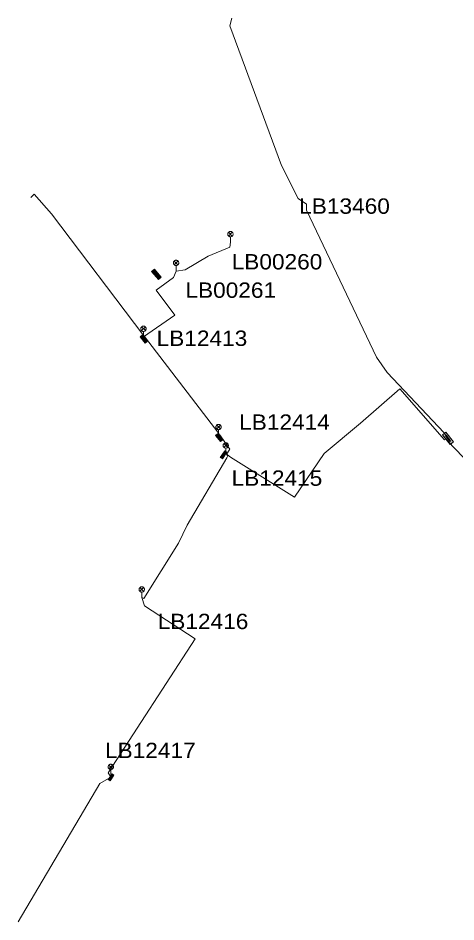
# Model space of a CAD drawing. Extents: x -688091 to -687952, y -973692 to -973558.
# Drawn here: x -688091.4 to -688029.8, y -973685.6 to -973558.3 of the extents above; entities that cross this region are included whole.
import ezdxf

# ---------------------------------------------------------------- set-up
doc = ezdxf.new("R2010")
doc.units = 0
doc.header["$LTSCALE"] = 0.87
doc.layers.add('1', color=7, linetype='Continuous', lineweight=13)

msp = doc.modelspace()

# ---------------------------------------------------------------- hatches: boundary and pattern name
at = {"layer": '1'}
for points in [[(-688071.655, -973595.126), (-688072.624, -973593.981), (-688072.242, -973593.658), (-688071.273, -973594.803)], [(-688071.696, -973594.768), (-688072.277, -973594.081), (-688072.201, -973594.016), (-688071.62, -973594.703)], [(-688073.515, -973604.067), (-688074.242, -973603.208), (-688073.956, -973602.966), (-688073.229, -973603.824)], [(-688073.546, -973603.798), (-688073.982, -973603.283), (-688073.925, -973603.234), (-688073.489, -973603.749)], [(-688062.906, -973617.935), (-688063.633, -973617.076), (-688063.347, -973616.834), (-688062.62, -973617.692)], [(-688062.937, -973617.666), (-688063.373, -973617.151), (-688063.316, -973617.102), (-688062.88, -973617.617)], [(-688030.592, -973618.351), (-688031.674, -973617.001), (-688031.224, -973616.64), (-688030.142, -973617.991)], [(-688030.628, -973617.937), (-688031.277, -973617.127), (-688031.187, -973617.055), (-688030.538, -973617.865)], [(-688062.959, -973620.178), (-688062.339, -973619.24), (-688062.026, -973619.446), (-688062.646, -973620.385)], [(-688062.71, -973620.073), (-688062.338, -973619.51), (-688062.276, -973619.551), (-688062.648, -973620.115)], [(-688078.721, -973665.574), (-688078.197, -973664.783), (-688077.933, -973664.958), (-688078.458, -973665.749)], [(-688078.511, -973665.486), (-688078.196, -973665.011), (-688078.143, -973665.046), (-688078.458, -973665.521)]]:
    msp.add_hatch(color=256, dxfattribs=at).paths.add_polyline_path(points)

# ---------------------------------------------------------------- linework, layer by layer
for p, q in [((-688061.795, -973588.455), (-688061.265, -973588.985)), ((-688061.795, -973588.985), (-688061.265, -973588.455)), ((-688061.53, -973589.87), (-688061.53, -973589.095)), ((-688069.445, -973592.505), (-688068.915, -973593.035)), ((-688069.445, -973593.035), (-688068.915, -973592.505)), ((-688069.18, -973593.92), (-688069.18, -973593.145)), ((-688074.038, -973601.781), (-688073.508, -973602.311)), ((-688074.038, -973602.311), (-688073.508, -973601.781)), ((-688073.773, -973603.196), (-688073.773, -973602.421)), ((-688063.467, -973615.63), (-688062.937, -973616.16)), ((-688063.467, -973616.16), (-688062.937, -973615.63)), ((-688063.202, -973617.045), (-688063.202, -973616.27)), ((-688062.447, -973618.23), (-688061.917, -973618.76)), ((-688062.447, -973618.76), (-688061.917, -973618.23)), ((-688062.182, -973619.645), (-688062.182, -973618.87)), ((-688074.275, -973638.515), (-688073.745, -973639.045)), ((-688074.275, -973639.045), (-688073.745, -973638.515)), ((-688074.01, -973639.93), (-688074.01, -973639.155)), ((-688078.645, -973663.525), (-688078.115, -973664.055)), ((-688078.645, -973664.055), (-688078.115, -973663.525)), ((-688078.38, -973664.94), (-688078.38, -973664.165))]:
    msp.add_line(p, q, dxfattribs=at)
for points in [[(-688061.349, -973558.277), (-688061.626, -973559.369), (-688054.331, -973579.05), (-688051.978, -973583.704), (-688050.82, -973584.51)], [(-688089.624, -973583.543), (-688089.144, -973583.093), (-688086.71, -973585.839), (-688073.712, -973603.033), (-688073.784, -973603.191)], [(-688050.82, -973584.51), (-688050.82, -973585.344), (-688040.947, -973606.062), (-688039.467, -973608.206), (-688031.454, -973616.703), (-688030.924, -973617.509)], [(-688069.18, -973593.92), (-688067.879, -973593.726), (-688064.671, -973591.828), (-688061.593, -973590.543), (-688061.53, -973589.87)], [(-688073.784, -973603.191), (-688069.349, -973600.138), (-688071.998, -973596.628), (-688069.529, -973594.837), (-688069.18, -973593.92)], [(-688073.784, -973603.191), (-688073.646, -973603.122), (-688063.167, -973616.788), (-688063.202, -973617.045)], [(-688062.182, -973619.645), (-688061.501, -973620.15), (-688052.521, -973625.758), (-688048.314, -973619.617), (-688043.211, -973615.339), (-688037.682, -973610.538), (-688031.377, -973617.691), (-688030.924, -973617.509)], [(-688063.202, -973617.045), (-688063.061, -973616.967), (-688061.604, -973619.01), (-688062.056, -973619.668), (-688062.182, -973619.645)], [(-688030.924, -973617.509), (-688030.924, -973617.873), (-688023.518, -973625.63), (-688020.453, -973628.618), (-688019.78, -973628.172)], [(-688074.01, -973639.93), (-688073.721, -973640.061), (-688068.821, -973632.243), (-688067.623, -973629.704), (-688062.047, -973620.222), (-688061.901, -973619.935), (-688062.182, -973619.645)], [(-688074.01, -973639.93), (-688073.617, -973641.103), (-688066.501, -973645.721), (-688078.752, -973664.628), (-688078.301, -973665.283)], [(-688091.419, -973685.626), (-688079.908, -973666.146), (-688078.353, -973665.248)]]:
    msp.add_lwpolyline(points, dxfattribs=at)
for points in [[(-688061.155, -973588.72), (-688061.161, -973588.655), (-688061.178, -973588.592), (-688061.205, -973588.533), (-688061.243, -973588.479), (-688061.289, -973588.433), (-688061.342, -973588.395), (-688061.402, -973588.368), (-688061.465, -973588.351), (-688061.53, -973588.345), (-688061.595, -973588.351), (-688061.658, -973588.368), (-688061.718, -973588.395), (-688061.771, -973588.433), (-688061.817, -973588.479), (-688061.855, -973588.533), (-688061.882, -973588.592), (-688061.899, -973588.655), (-688061.905, -973588.72), (-688061.899, -973588.785), (-688061.882, -973588.848), (-688061.855, -973588.908), (-688061.817, -973588.961), (-688061.771, -973589.007), (-688061.718, -973589.045), (-688061.658, -973589.072), (-688061.595, -973589.089), (-688061.53, -973589.095), (-688061.465, -973589.089), (-688061.402, -973589.072), (-688061.342, -973589.045), (-688061.289, -973589.007), (-688061.243, -973588.961), (-688061.205, -973588.908), (-688061.178, -973588.848), (-688061.161, -973588.785)], [(-688068.805, -973592.77), (-688068.811, -973592.705), (-688068.828, -973592.642), (-688068.855, -973592.582), (-688068.893, -973592.529), (-688068.939, -973592.483), (-688068.992, -973592.445), (-688069.052, -973592.418), (-688069.115, -973592.401), (-688069.18, -973592.395), (-688069.245, -973592.401), (-688069.308, -973592.418), (-688069.368, -973592.445), (-688069.421, -973592.483), (-688069.467, -973592.529), (-688069.505, -973592.582), (-688069.532, -973592.642), (-688069.549, -973592.705), (-688069.555, -973592.77), (-688069.549, -973592.835), (-688069.532, -973592.898), (-688069.505, -973592.958), (-688069.467, -973593.011), (-688069.421, -973593.057), (-688069.368, -973593.095), (-688069.308, -973593.122), (-688069.245, -973593.139), (-688069.18, -973593.145), (-688069.115, -973593.139), (-688069.052, -973593.122), (-688068.992, -973593.095), (-688068.939, -973593.057), (-688068.893, -973593.011), (-688068.855, -973592.958), (-688068.828, -973592.898), (-688068.811, -973592.835)], [(-688071.655, -973595.126), (-688072.624, -973593.981), (-688072.242, -973593.658), (-688071.273, -973594.803)], [(-688071.655, -973595.126), (-688072.624, -973593.981), (-688072.242, -973593.658), (-688071.273, -973594.803)], [(-688071.696, -973594.768), (-688072.277, -973594.081), (-688072.201, -973594.016), (-688071.62, -973594.703)], [(-688073.398, -973602.046), (-688073.404, -973601.981), (-688073.421, -973601.918), (-688073.448, -973601.858), (-688073.486, -973601.805), (-688073.532, -973601.759), (-688073.586, -973601.721), (-688073.645, -973601.694), (-688073.708, -973601.677), (-688073.773, -973601.671), (-688073.838, -973601.677), (-688073.901, -973601.694), (-688073.96, -973601.721), (-688074.014, -973601.759), (-688074.06, -973601.805), (-688074.098, -973601.858), (-688074.125, -973601.918), (-688074.142, -973601.981), (-688074.148, -973602.046), (-688074.142, -973602.111), (-688074.125, -973602.174), (-688074.098, -973602.234), (-688074.06, -973602.287), (-688074.014, -973602.333), (-688073.96, -973602.371), (-688073.901, -973602.398), (-688073.838, -973602.415), (-688073.773, -973602.421), (-688073.708, -973602.415), (-688073.645, -973602.398), (-688073.586, -973602.371), (-688073.532, -973602.333), (-688073.486, -973602.287), (-688073.448, -973602.234), (-688073.421, -973602.174), (-688073.404, -973602.111)], [(-688073.515, -973604.067), (-688074.242, -973603.208), (-688073.956, -973602.966), (-688073.229, -973603.824)], [(-688073.515, -973604.067), (-688074.242, -973603.208), (-688073.956, -973602.966), (-688073.229, -973603.824)], [(-688073.546, -973603.798), (-688073.982, -973603.283), (-688073.925, -973603.234), (-688073.489, -973603.749)], [(-688062.827, -973615.895), (-688062.833, -973615.83), (-688062.85, -973615.767), (-688062.877, -973615.708), (-688062.915, -973615.654), (-688062.961, -973615.608), (-688063.014, -973615.57), (-688063.074, -973615.543), (-688063.137, -973615.526), (-688063.202, -973615.52), (-688063.267, -973615.526), (-688063.33, -973615.543), (-688063.39, -973615.57), (-688063.443, -973615.608), (-688063.489, -973615.654), (-688063.527, -973615.708), (-688063.554, -973615.767), (-688063.571, -973615.83), (-688063.577, -973615.895), (-688063.571, -973615.96), (-688063.554, -973616.023), (-688063.527, -973616.082), (-688063.489, -973616.136), (-688063.443, -973616.182), (-688063.39, -973616.22), (-688063.33, -973616.247), (-688063.267, -973616.264), (-688063.202, -973616.27), (-688063.137, -973616.264), (-688063.074, -973616.247), (-688063.014, -973616.22), (-688062.961, -973616.182), (-688062.915, -973616.136), (-688062.877, -973616.082), (-688062.85, -973616.023), (-688062.833, -973615.96)], [(-688062.906, -973617.935), (-688063.633, -973617.076), (-688063.347, -973616.834), (-688062.62, -973617.692)], [(-688062.906, -973617.935), (-688063.633, -973617.076), (-688063.347, -973616.834), (-688062.62, -973617.692)], [(-688062.937, -973617.666), (-688063.373, -973617.151), (-688063.316, -973617.102), (-688062.88, -973617.617)], [(-688030.592, -973618.351), (-688031.674, -973617.001), (-688031.224, -973616.64), (-688030.142, -973617.991)], [(-688030.592, -973618.351), (-688031.674, -973617.001), (-688031.224, -973616.64), (-688030.142, -973617.991)], [(-688030.628, -973617.937), (-688031.277, -973617.127), (-688031.187, -973617.055), (-688030.538, -973617.865)], [(-688061.807, -973618.495), (-688061.813, -973618.43), (-688061.83, -973618.367), (-688061.857, -973618.307), (-688061.895, -973618.254), (-688061.941, -973618.208), (-688061.994, -973618.17), (-688062.054, -973618.143), (-688062.117, -973618.126), (-688062.182, -973618.12), (-688062.247, -973618.126), (-688062.31, -973618.143), (-688062.37, -973618.17), (-688062.423, -973618.208), (-688062.469, -973618.254), (-688062.507, -973618.307), (-688062.534, -973618.367), (-688062.551, -973618.43), (-688062.557, -973618.495), (-688062.551, -973618.56), (-688062.534, -973618.623), (-688062.507, -973618.682), (-688062.469, -973618.736), (-688062.423, -973618.782), (-688062.37, -973618.82), (-688062.31, -973618.847), (-688062.247, -973618.864), (-688062.182, -973618.87), (-688062.117, -973618.864), (-688062.054, -973618.847), (-688061.994, -973618.82), (-688061.941, -973618.782), (-688061.895, -973618.736), (-688061.857, -973618.682), (-688061.83, -973618.623), (-688061.813, -973618.56)], [(-688062.959, -973620.178), (-688062.339, -973619.24), (-688062.026, -973619.446), (-688062.646, -973620.385)], [(-688062.959, -973620.178), (-688062.339, -973619.24), (-688062.026, -973619.446), (-688062.646, -973620.385)], [(-688062.71, -973620.073), (-688062.338, -973619.51), (-688062.276, -973619.551), (-688062.648, -973620.115)], [(-688073.635, -973638.78), (-688073.641, -973638.715), (-688073.658, -973638.652), (-688073.685, -973638.592), (-688073.723, -973638.539), (-688073.769, -973638.493), (-688073.822, -973638.455), (-688073.882, -973638.428), (-688073.945, -973638.411), (-688074.01, -973638.405), (-688074.075, -973638.411), (-688074.138, -973638.428), (-688074.198, -973638.455), (-688074.251, -973638.493), (-688074.297, -973638.539), (-688074.335, -973638.592), (-688074.362, -973638.652), (-688074.379, -973638.715), (-688074.385, -973638.78), (-688074.379, -973638.845), (-688074.362, -973638.908), (-688074.335, -973638.968), (-688074.297, -973639.021), (-688074.251, -973639.067), (-688074.198, -973639.105), (-688074.138, -973639.132), (-688074.075, -973639.149), (-688074.01, -973639.155), (-688073.945, -973639.149), (-688073.882, -973639.132), (-688073.822, -973639.105), (-688073.769, -973639.067), (-688073.723, -973639.021), (-688073.685, -973638.968), (-688073.658, -973638.908), (-688073.641, -973638.845)], [(-688078.005, -973663.79), (-688078.011, -973663.725), (-688078.028, -973663.662), (-688078.055, -973663.602), (-688078.093, -973663.549), (-688078.139, -973663.503), (-688078.192, -973663.465), (-688078.252, -973663.438), (-688078.315, -973663.421), (-688078.38, -973663.415), (-688078.445, -973663.421), (-688078.508, -973663.438), (-688078.568, -973663.465), (-688078.621, -973663.503), (-688078.667, -973663.549), (-688078.705, -973663.602), (-688078.732, -973663.662), (-688078.749, -973663.725), (-688078.755, -973663.79), (-688078.749, -973663.855), (-688078.732, -973663.918), (-688078.705, -973663.977), (-688078.667, -973664.031), (-688078.621, -973664.077), (-688078.568, -973664.115), (-688078.508, -973664.142), (-688078.445, -973664.159), (-688078.38, -973664.165), (-688078.315, -973664.159), (-688078.252, -973664.142), (-688078.192, -973664.115), (-688078.139, -973664.077), (-688078.093, -973664.031), (-688078.055, -973663.977), (-688078.028, -973663.918), (-688078.011, -973663.855)], [(-688078.721, -973665.574), (-688078.197, -973664.783), (-688077.933, -973664.958), (-688078.458, -973665.749)], [(-688078.721, -973665.574), (-688078.197, -973664.783), (-688077.933, -973664.958), (-688078.458, -973665.749)], [(-688078.511, -973665.486), (-688078.196, -973665.011), (-688078.143, -973665.046), (-688078.458, -973665.521)]]:
    msp.add_lwpolyline(points, close=True, dxfattribs=at)

# ---------------------------------------------------------------- texts
at = {"layer": '1', "width": 1.1}
for s, p in [('LB13460', (-688051.854, -973585.851)), ('LB00260', (-688061.357, -973593.695)), ('LB00261', (-688067.865, -973597.693)), ('LB12413', (-688071.922, -973604.471)), ('LB12414', (-688060.309, -973616.286)), ('LB12415', (-688061.365, -973624.176)), ('LB12416', (-688071.772, -973644.371)), ('LB12417', (-688079.189, -973662.553))]:
    msp.add_text(s, height=2.167, dxfattribs=at).set_placement(p)

doc.saveas('drawing.dxf')
